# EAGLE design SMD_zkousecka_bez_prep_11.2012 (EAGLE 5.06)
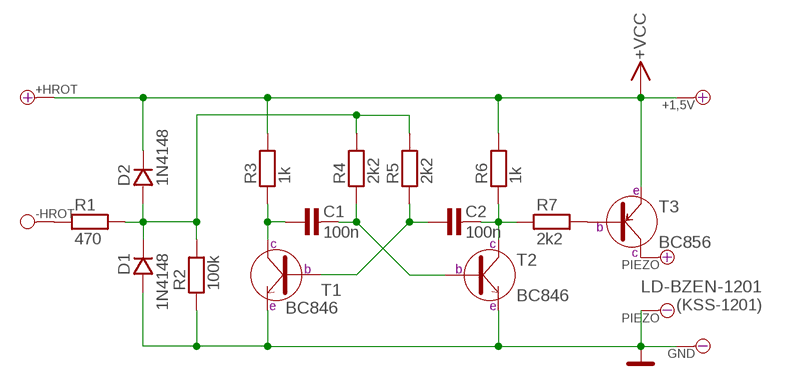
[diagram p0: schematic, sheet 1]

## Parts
+1,5V  PAD_1+  [PAD_1]
+HROT  PAD_1+  [PAD_1]
-HROT  PAD_1  [PAD_1]
C1  100n  C-KERAMIK_SMD_0805  [0805]
C2  100n  C-KERAMIK_SMD_0805  [0805]
D1  1N4148  1N4148_SOD80  [SOD-80]
D2  1N4148  1N4148_SOD80  [SOD-80]
GND  PAD_1-  [PAD_1]
PIEZO  LD-BZEN-1201  PAD_2+-  [PAD_2+-]
R1  470  R_SMD_1206  [1206]
R2  100k  R_SMD_1206  [1206]
R3  1k  R_SMD_1206  [1206]
R4  2k2  R_SMD_1206  [1206]
R5  2k2  R_SMD_1206  [1206]
R6  1k  R_SMD_1206  [1206]
R7  2k2  R_SMD_1206  [1206]
T1  BC846  [SOT-23]
T2  BC846  [SOT-23]
T3  BC856  [SOT-23]

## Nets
GND: D1.A GND.1(-) PIEZO.- R2.1 T1.2(E) T2.2(E)
N$1: C1.1 R3.1 T1.3(C)
N$2: C1.2 R4.1 T2.1(B)
N$3: C2.1 R5.1 T1.1(B)
N$4: R7.2 T3.1(B)
N$5: -HROT.1 R1.1
N$6: PIEZO.+ T3.3(C)
N$8: C2.2 R6.1 R7.1 T2.3(C)
N$10: D1.K D2.A R1.2 R2.2 R4.2 R5.2
VCC: +1,5V.1(+) +HROT.1(+) D2.K R3.2 R6.2 T3.2(E) ; supply symbol labelled +VCC

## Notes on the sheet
- LD-BZEN-1201
- (KSS-1201)

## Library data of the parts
+1,5V +HROT = #PaJa_31:PAD_1+: Pajeci bod - 2,54 mm prumer, + kladny
-HROT = #PaJa_31:PAD_1: Pajeci bod - 2,54 mm prumer
C1 C2 = #PaJa_31:C-KERAMIK: Kondenzator - keramicky
D1 D2 = #PaJa_31:1N4148: Univerzalni dioda - 0,15A, 75V
GND = #PaJa_31:PAD_1-: Pajeci bod - 2,54 mm prumer, - zaporny
PIEZO = #PaJa_31:PAD_2+-: Pajeci bod - 2,54 mm prumer, + a - , napajeci
R1-R7 = #PaJa_31:R: Rezistor
T1 T2 = #PaJa_31:BC846: SMD tranzistor - NPN - ekv. BC546
T3 = #PaJa_31:BC856: SMD tranzistor - PNP - ekv. BC556

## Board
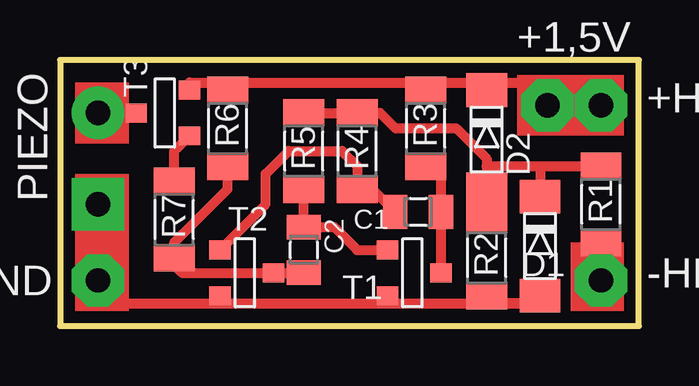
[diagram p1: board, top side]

Size 24.12 x 11.1 mm. Coordinates in mm from the lower left corner, seen from the top.
Outline: 0,0 24.12,0 24.12,11.1 0,11.1 0,0
Copper layers (1*16): Top 0.035mm / dielectric 1.5mm / Bottom 0.035mm
Design rules "default": minimum track width 10mil, minimum drill 24mil, track to track 8mil, track to pad 8mil, pad to pad 8mil, via to via 8mil, smd to smd 8mil, copper to edge 40mil, drill to drill 8mil, minimum pad ring 10mil, minimum via ring 8mil, stop-mask expansion 4mil, vias tented up to drill 0mil, thermal gap 10mil

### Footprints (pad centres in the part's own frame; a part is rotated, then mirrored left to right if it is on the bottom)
PAD_1 = drill 1.016 pad 2.184 octagon: 1 0,0
0805 = smd 1.016 x 1.422: 1 -0.953,0; 2 0.953,0
SOD-80 = smd 1.397 x 1.702: A 1.905,0; K -2.223,0
PAD_2+- = drill 1.016 pad 2.184 round: + -1.905,0 | drill 1.016 pad 2.184 square: - 1.905,0
1206 = smd 1.143 x 1.702: 1 -1.587,0; 2 1.587,0
SOT-23 = smd 0.787 x 0.889: 1 -0.953,-0.953; 2 0.953,-0.953; 3 0,1.27

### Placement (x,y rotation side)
+1,5V  20.32,9.21 0 top
+HROT  22.54,9.21 270 top
-HROT  22.54,1.91 270 top
C1  14.92,4.76 180 top
C2  10.16,3.17 270 top
D1  20,3.17 270 top
D2  17.78,7.62 270 top
GND  1.59,1.91 0 top
PIEZO  1.59,6.99 270 top
R1  22.54,5.08 90 top
R2  17.78,2.86 90 top
R3  15.24,8.26 90 top
R4  12.38,7.3 90 top
R5  10.16,7.3 90 top
R6  6.99,8.26 90 top
R7  4.76,4.45 90 top
T1  14.61,2.22 270 top
T2  7.62,2.22 270 top
T3  4.45,8.89 90 top

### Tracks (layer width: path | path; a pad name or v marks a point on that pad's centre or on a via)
GND
  Top 0.406: 6.67,0.95 13.65,0.95 | 13.65,0.95 20,0.95 | 13.65,0.95 T1.2 | 20,0.95 D1.A | 20,0.95 17.78,0.95 R2.1 | 6.67,0.95 2.54,0.95 GND.1 PIEZO.- | 6.67,0.95 T2.2
N$1
  Top 0.406: R3.1 15.88,6.67 C1.1 T1.3
N$2
  Top 0.406: C1.2 13.02,5.71 R4.1 12.38,6.67 11.75,7.3 9.53,7.3 8.57,6.35 8.57,5.08 T2.1
N$3
  Top 0.406: R5.1 C2.1 11.43,4.13 12.38,3.17 T1.1
N$4
  Top 0.406: R7.2 4.76,7.3 T3.1
N$5
  Top 0.406: -HROT.1 R1.1
N$6
  Top 0.406: PIEZO.+ T3.3
N$8
  Top 0.406: C2.2 T2.3 5.08,2.22 4.76,2.54 R7.1 4.76,3.49 6.99,5.71 R6.1
N$10
  Top 0.406: D2.A R2.2 | D2.A 17.78,6.03 | R5.2 R4.2 13.34,8.89 13.97,8.26 16.51,8.26 17.78,6.99 17.78,6.67 | 17.78,6.67 D2.A | 20,6.67 R1.2 | 20,6.67 D1.K | 17.78,6.67 20,6.67
VCC
  Top 0.406: 17.78,10.16 D2.K | 15.24,10.16 17.78,10.16 | 15.24,10.16 R3.2 | 6.67,10.16 15.24,10.16 | 6.67,10.16 R6.2 | 6.67,10.16 5.4,10.16 T3.2 | 17.78,10.16 20.32,10.16 | 20.32,10.16 21.59,10.16 +HROT.1 | 20.32,10.16 +1,5V.1
(copper drawn outside any net)
  shapes: Top area x4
